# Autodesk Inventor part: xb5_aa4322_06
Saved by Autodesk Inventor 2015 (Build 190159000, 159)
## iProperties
Created: 2018-05
Part Number: xb5_aa4322_06
Checked By: TraceParts S.A.
Material: Generic
Catalog Web Link: www.traceparts.com
Document SubType Name: Modeling
Designer: TraceParts
Density: 1 g/cm^3
Appearance: Default
Company: TraceParts S.A.
Author: TraceParts
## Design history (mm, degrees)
feature "xb5_aa4322_06.ipt"
body "Solid1"
